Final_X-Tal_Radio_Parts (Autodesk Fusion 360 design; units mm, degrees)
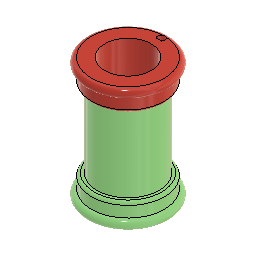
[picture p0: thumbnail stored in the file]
part number: 2026-06-11-08-03-41-367
part number: 2026-06-11-08-08-01-959
part number: 2026-06-11-08-13-43-022
part number: 2026-06-11-09-52-00-840
part number: 2026-06-11-10-06-28-813
part number: 2026-06-11-10-12-27-439
part number: 2026-06-11-10-33-16-979
part number: 2026-06-11-10-49-01-634
part number: 2026-06-11-11-00-53-288
part number: 2026-06-11-13-21-08-521
part number: 2026-06-11-14-49-13-048
sketch "Skt_SpoleForm_1C" plane through (0, 0, 0) normal (0, 0, 1) x axis (1, 0, 0)
  line L1 (0, 9) -> (0, 0)
  circle C1 centre (0, 0) radius 6
  circle C2 centre (0, 0) radius 8
  circle C3 centre (0, 0) radius 9
  circle C4 centre (0, 0) radius 5.1
  circle C5 centre (0, 7.3) radius 0.8
  circle C6 centre (0, 0) radius 6.8
  point P4 (0, 0)
  point P5 (0, 0)
  point P7 (0, 0)
  point P10 (0, 0)
  point P2 (0, 0)
  point P8 (0, 0)
  point P6 (0, 9)
  point P3 (0, 7.3)
  point P1 (0, 0)
  point P9 (0, 0)
  point P11 (0, 0)
  coincident P4 P5
  concentric C4 C6
  concentric C3 C4
  concentric C2 C6
  coincident P7 P10
  vertical L1
  concentric C1 C3
  coincident P2 P8
  coincident P6 C3
  coincident P3 L1
  coincident P1 P9
  dimension "d78" diameter C4 = 10.2
  dimension "d79" diameter C6 = 13.6
  dimension "d80" diameter C3 = 18
  dimension "d81" diameter C2 = 16
  dimension "d82" diameter C5 = 1.6
  dimension "d83" diameter C1 = 12
  dimension "d84" distance P3 P11 = 7.3
sketch "Skt_Knap_VarioCap" plane through (0, 0, 0) normal (0, 0, 1) x axis (1, 0, 0)
  line L1 (-2.6, -1.6882) -> (-2.6, 1.6882)
  circle C1 centre (0, 0) radius 10
  circle C2 centre (0, 0) radius 6
  circle C3 centre (0, 0) radius 12
  circle C4 centre (0, 0) radius 3.1
  point P2 (0, 0)
  point P3 (0, 0)
  point P7 (-2.6, 1.6882)
  point P5 (-2.6, -1.6882)
  point P4 (0, 0)
  point P1 (0, 0)
  point P6 (0, 0)
  coincident P2 P3
  coincident P7 C4
  coincident P5 C4
  vertical L1
  coincident P3 P4
  concentric C1 C4
  concentric C2 C3
  coincident P1 P6
  dimension "d85" diameter C4 = 6.2
  dimension "d86" distance P2 L1 = 2.6
  dimension "d87" diameter C2 = 12
  dimension "d88" diameter C1 = 20
  dimension "d89" diameter C3 = 24
sketch "Sketch1" plane through (0, 0, 0) normal (0, 0, 1) x axis (1, 0, 0)
  line L1 (23.2274, -19) -> (-23.2274, -19)
  line L2 (23.2274, 19) -> (-23.2274, 19)
  line L3 (30.5, 21.5) -> (-30.5, 21.5)
  line L4 (0.5, 16) -> (-23.2274, 16)
  line L5 (-30.5, 21.5) -> (30.5, -21.5)
  line L6 (-30.5, 21.5) -> (-30.5, -21.5)
  line L7 (4.5, -12) -> (4.5, 12)
  line L8 (30.5, 21.5) -> (-30.5, -21.5)
  line L9 (-30.5, -21.5) -> (30.5, -21.5)
  line L10 (0.5, -16) -> (-23.2274, -16)
  line L11 (23.2274, -16) -> (11.5, -16)
  line L12 (30.5, -21.5) -> (30.5, 21.5)
  line L13 (23.2274, 16) -> (11.5, 16)
  line L14 (7.5, -12) -> (7.5, 12)
  circle C1 centre (-26.5, -17.5) radius 3.6
  circle C2 centre (-26.5, 17.5) radius 1.6
  arc A1 centre (0.5, 12) radius 4 clockwise from (0.5, 16) to (4.5, 12)
  circle C3 centre (-26.5, -17.5) radius 1.6
  arc A2 centre (11.5, 12) radius 4 clockwise from (7.5, 12) to (11.5, 16)
  circle C4 centre (26.5, -17.5) radius 3.6
  circle C5 centre (26.5, 17.5) radius 1.6
  circle C6 centre (26.5, 17.5) radius 3.6
  circle C7 centre (26.5, -17.5) radius 1.6
  arc A3 centre (11.5, -12) radius 4 clockwise from (11.5, -16) to (7.5, -12)
  arc A4 centre (0.5, -12) radius 4 clockwise from (4.5, -12) to (0.5, -16)
  circle C8 centre (-26.5, 17.5) radius 3.6
  point P9 (0, 0)
  point P2 (0, 0)
  point P29 (-23.2274, 16)
  point P35 (23.2274, 16)
  point P28 (-23.2274, 19)
  point P27 (23.2274, 19)
  point P31 (-23.2274, -19)
  point P34 (23.2274, -19)
  point P30 (-23.2274, -16)
  point P33 (23.2274, -16)
  point P1 (0, 0)
  point P5 (-30.5, 21.5)
  point P10 (30.5, 21.5)
  point P4 (-30.5, -21.5)
  point P6 (26.5, 17.5)
  point P12 (26.5, -17.5)
  point P8 (-26.5, 17.5)
  point P7 (-26.5, -17.5)
  point P14 (26.5, 17.5)
  horizontal L9
  perpendicular L6 L9
  parallel L3 L9
  parallel L6 L12
  coincident P9 L5
  coincident P9 L8
  coincident P2 P9
  concentric C2 C8
  concentric C5 C6
  concentric C1 C3
  concentric C4 C7
  coincident P29 C8
  coincident P35 C6
  horizontal L4
  coincident P28 C8
  coincident P27 C6
  parallel L2 L3
  coincident P31 C1
  coincident P34 C4
  parallel L1 L9
  coincident P30 C1
  coincident P33 C4
  horizontal L10
  perpendicular L10 L14
  perpendicular L7 L10
  collinear L4 L13
  collinear L10 L11
  tangent A2 L14
  tangent A2 L13
  tangent A3 L14
  tangent L11 A3
  equal A2 A3
  tangent L7 A4
  tangent L10 A4
  equal A2 A4
  tangent L7 A1
  tangent L4 A1
  equal A1 A2
  coincident P1 P2
  dimension "d1" distance P5 P10 = 61
  dimension "d2" distance P4 P5 = 43
  dimension "d3" diameter C2 = 3.2
  dimension "d4" diameter C5 = 3.2
  dimension "d5" diameter C3 = 3.2
  dimension "d6" diameter C7 = 3.2
  dimension "d7" distance P6 L12 = 4
  dimension "d8" distance P12 L12 = 4 (= "d7")
  dimension "d9" distance P6 L3 = 4 (= "d7")
  dimension "d10" distance P8 L6 = 4 (= "d7")
  dimension "d11" distance P12 L9 = 4 (= "d7")
  dimension "d12" distance P7 L6 = 4 (= "d7")
  dimension "d13" distance P8 L3 = 4 (= "d7")
  dimension "d14" distance P7 L9 = 4 (= "d7")
  dimension "d15" diameter C8 = 7.2
  dimension "d16" diameter C6 = 7.2
  dimension "d17" diameter C1 = 7.2
  dimension "d18" diameter C4 = 7.2
  dimension "d19" distance L2 L4 = 3
  dimension "d20" distance P2 P14 = 17.5
  dimension "d21" distance P2 L4 = 16
  dimension "d22" distance P2 L10 = 16
  dimension "d23" distance L1 L10 = 3
  dimension "d24" distance L12 L14 = 23
  dimension "d25" distance L7 L14 = 3
  dimension "d26" radius A2 = 4
extrude "Extrude1" new body sketch "Sketch1" profile of L1 L2 L4 C1 L7 A1 L10 A2 C4 L11 C6 A3 A4 L13 L14 C8 along normal blind 1.6
extrude "Extrude2" add sketch "Sketch1" profile of C1 C2 C3 C4 C5 C6 C7 C8 along normal blind 2.4
fillet "Fillet1" radius 4
sketch "Sketch1" plane through (0, 0, 0) normal (0, 0, 1) x axis (1, 0, 0)
  line L1 (23.2274, -19) -> (-23.2274, -19)
  line L2 (23.2274, 19) -> (-23.2274, 19)
  line L3 (-30.5, 21.5) -> (-30.5, -21.5)
  line L4 (0.5, -16) -> (-23.2274, -16)
  line L5 (30.5, 21.5) -> (-30.5, 21.5)
  line L6 (30.5, -21.5) -> (30.5, 21.5)
  line L7 (-30.5, 21.5) -> (30.5, -21.5)
  line L8 (23.2274, -16) -> (11.5, -16)
  line L9 (23.2274, 16) -> (11.5, 16)
  line L10 (-30.5, -21.5) -> (30.5, -21.5)
  line L11 (30.5, 21.5) -> (-30.5, -21.5)
  line L12 (0.5, 16) -> (-23.2274, 16)
  line L13 (-26, -5) -> (-26, -13.9349)
  line L14 (-29, -4) -> (-29, -14.9096)
  line L15 (0.5, 0) -> (-25, 0)
  line L16 (26.1, 0) -> (11.5, 0)
  line L17 (7.5, 4) -> (7.5, 12)
  line L18 (7.5, -12) -> (7.5, -3)
  line L19 (4.5, 4) -> (4.5, 12)
  line L20 (4.5, -12) -> (4.5, -3)
  line L21 (27.5, -14.0417) -> (27.5, -5)
  line L22 (30.1, -4) -> (30.1, -17.5)
  line L23 (25.5, -3) -> (-24, -3)
  arc A1 centre (11.5, 12) radius 4 clockwise from (7.5, 12) to (11.5, 16)
  circle C1 centre (26.5, -17.5) radius 3.6
  arc A2 centre (0.5, -12) radius 4 clockwise from (4.5, -12) to (0.5, -16)
  circle C2 centre (26.5, 17.5) radius 3.6
  circle C3 centre (26.5, -17.5) radius 1.6
  circle C4 centre (26.5, 17.5) radius 1.6
  arc A3 centre (0.5, 12) radius 4 clockwise from (0.5, 16) to (4.5, 12)
  circle C5 centre (-26.5, 17.5) radius 3.6
  circle C6 centre (-26.5, -17.5) radius 3.6
  circle C7 centre (-26.5, -17.5) radius 1.6
  arc A4 centre (11.5, -12) radius 4 clockwise from (11.5, -16) to (7.5, -12)
  circle C8 centre (-26.5, 17.5) radius 1.6
  arc A5 centre (0.5, 4) radius 4 clockwise from (4.5, 4) to (0.5, 0)
  arc A6 centre (11.5, 4) radius 4 clockwise from (11.5, 0) to (7.5, 4)
  arc A7 centre (25.5, -5) radius 2 clockwise from (25.5, -3) to (27.5, -5)
  arc A8 centre (-25, -4) radius 4 clockwise from (-29, -4) to (-25, 0)
  arc A9 centre (-24, -5) radius 2 clockwise from (-26, -5) to (-24, -3)
  arc A10 centre (26.1, -4) radius 4 clockwise from (26.1, 0) to (30.1, -4)
  point P4 (0, 0)
  point P19 (0, 0)
  point P15 (-23.2274, 16)
  point P11 (23.2274, 16)
  point P2 (-23.2274, 19)
  point P22 (23.2274, 19)
  point P13 (-23.2274, -19)
  point P10 (23.2274, -19)
  point P12 (-23.2274, -16)
  point P14 (23.2274, -16)
  point P30 (0, 0)
  point P1 (0, 0)
  point P37 (-26, -13.9349)
  point P38 (-29, -14.9096)
  point P39 (7.5, -3)
  point P40 (4.5, -3)
  point P41 (27.5, -14.0417)
  point P42 (30.1, -17.5)
  point P9 (30.5, 21.5)
  point P21 (-30.5, 21.5)
  point P18 (-30.5, -21.5)
  point P17 (26.5, 17.5)
  point P6 (26.5, -17.5)
  point P3 (-26.5, 17.5)
  point P7 (-26.5, -17.5)
  point P31 (26.5, 17.5)
  horizontal L10
  perpendicular L3 L10
  parallel L5 L10
  parallel L3 L6
  coincident P4 L7
  coincident P4 L11
  coincident P4 P19
  concentric C5 C8
  concentric C2 C4
  concentric C6 C7
  concentric C1 C3
  coincident P15 C5
  coincident P11 C2
  horizontal L12
  coincident P2 C5
  coincident P22 C2
  parallel L2 L5
  coincident P13 C6
  coincident P10 C1
  parallel L1 L10
  coincident P12 C6
  coincident P14 C1
  horizontal L4
  perpendicular L4 L18
  perpendicular L4 L20
  collinear L9 L12
  collinear L4 L8
  tangent A1 L17
  tangent A1 L9
  tangent A4 L18
  tangent L8 A4
  equal A1 A4
  tangent A2 L20
  tangent A2 L4
  equal A1 A2
  tangent A3 L19
  tangent A3 L12
  equal A1 A3
  coincident P19 P30
  coincident P1 P30
  coincident C6 P37
  parallel L3 L13
  perpendicular L6 L16
  coincident C6 P38
  perpendicular L14 L23
  collinear L15 L16
  coincident P39 L23
  collinear L17 L18
  coincident P40 L23
  collinear L19 L20
  coincident C1 P41
  perpendicular L21 L23
  coincident C1 P42
  tangent L15 A5
  tangent L19 A5
  tangent L16 A6
  tangent L17 A6
  equal A5 A6
  tangent L21 A7
  tangent L23 A7
  tangent L15 A8
  tangent L14 A8
  tangent L23 A9
  tangent L13 A9
  tangent L22 A10
  tangent L16 A10
  dimension "d33" distance P9 P21 = 61
  dimension "d34" distance P18 P21 = 43
  dimension "d35" diameter C8 = 3.2
  dimension "d36" diameter C4 = 3.2
  dimension "d37" diameter C7 = 3.2
  dimension "d38" diameter C3 = 3.2
  dimension "d39" distance P17 L6 = 4
  dimension "d40" distance P6 L6 = 4 (= "d7")
  dimension "d41" distance P17 L5 = 4 (= "d7")
  dimension "d42" distance P3 L3 = 4 (= "d7")
  dimension "d43" distance P6 L10 = 4 (= "d7")
  dimension "d44" distance P7 L3 = 4 (= "d7")
  dimension "d45" distance P3 L5 = 4 (= "d7")
  dimension "d46" distance P7 L10 = 4 (= "d7")
  dimension "d47" diameter C5 = 7.2
  dimension "d48" diameter C2 = 7.2
  dimension "d49" diameter C6 = 7.2
  dimension "d50" diameter C1 = 7.2
  dimension "d51" distance L2 L12 = 3
  dimension "d52" distance P19 P31 = 17.5
  dimension "d53" distance P19 L12 = 16
  dimension "d54" distance P19 L4 = 16
  dimension "d55" distance L1 L4 = 3
  dimension "d56" distance L6 L17 = 23
  dimension "d57" distance L17 L19 = 3
  dimension "d58" radius A1 = 4
  dimension "d60" distance L15 L23 = 3
  dimension "d61" distance L3 L13 = 4.5
  dimension "d62" distance L13 L14 = 3
  dimension "d63" distance L6 L21 = 3
  dimension "d64" distance L6 L22 = 0.4
  dimension "d65" distance L10 L23 = 18.5
  dimension "d66" radius A5 = 4
  dimension "d67" radius A7 = 2
  dimension "d73" radius A8 = 4
  dimension "d74" radius A9 = 2
  dimension "d75" radius A10 = 4
extrude "Extrude1" new body sketch "Sketch1" profile of A1 C1 C2 L20 L2 A3 C5 C6 L18 L9 L12 L13 L23 L16 L14 L21 L22 A5 A6 A7 along normal blind 1.6
extrude "Extrude2" add sketch "Sketch1" profile of C1 C2 C3 C4 C5 C6 C7 C8 along normal blind 2.4
fillet "Fillet1" radius 4
extrude "Extrude1" new body sketch "Skt_SpoleForm_1C" profile of C2 C3 C5 along normal blind 2
extrude "Extrude2" add sketch "Skt_SpoleForm_1C" profile of C2 C5 C6 along normal blind 5
extrude "Extrude3" add sketch "Skt_SpoleForm_1C" profile of C1 C5 C6 along normal blind 22
extrude "Extrude4" add sketch "Skt_SpoleForm_1C" profile of C1 C4 along normal blind 19
fillet "Fillet1" radius 1 0.6
extrude "Extrude1" new body sketch "Skt_SpoleForm_1C" profile of C2 C3 C5 along normal blind 2
extrude "Extrude2" add sketch "Skt_SpoleForm_1C" profile of C2 C5 C6 along normal blind 5
extrude "Extrude3" add sketch "Skt_SpoleForm_1C" profile of C1 C5 C6 along normal blind 32
extrude "Extrude4" add sketch "Skt_SpoleForm_1C" profile of C1 C4 along normal blind 29
fillet "Fillet1" radius 1 0.6
extrude "Extrude1" new body sketch "Skt_SpoleForm_1C" profile of C2 C3 C5 blind -2 from offset 27
extrude "Extrude2" add sketch "Skt_SpoleForm_1C" profile of C1 C2 C5 C6 blind -5 from offset 27
extrude "Extrude3" add sketch "Skt_SpoleForm_1C" profile of C1 C4 blind -8 from offset 27
fillet "Fillet1" radius 1 0.6 0.4
sketch "Sketch1" plane through (0, 0, 0) normal (0, 0, 1) x axis (1, 0, 0)
  line L1 (33, -5) -> (33, 5)
  line L2 (32, 18) -> (28, 18)
  line L3 (35, -15) -> (35, 15)
  line L4 (27, 5) -> (27, -5)
  line L5 (17, 6) -> (17, -6)
  line L6 (13, 4) -> (-11.0133, 4)
  line L7 (25, 15) -> (25, -15)
  line L8 (32, 6) -> (28, 6)
  line L9 (17, 6) -> (-13.0201, 6)
  line L10 (13, -4) -> (13, 4)
  line L11 (17, -6) -> (-13.0201, -6)
  line L12 (-11.0133, -4) -> (13, -4)
  line L13 (28, -18) -> (32, -18)
  line L14 (28, -6) -> (32, -6)
  line L15 (-17, 0) -> (0, 0)
  circle C1 centre (30, -12) radius 1.75
  arc A1 centre (28, 15) radius 3 clockwise from (25, 15) to (28, 18)
  arc A2 centre (28, -15) radius 3 clockwise from (28, -18) to (25, -15)
  arc A3 centre (32, 15) radius 3 clockwise from (32, 18) to (35, 15)
  circle C2 centre (-17, 0) radius 7.2
  circle C3 centre (30, 12) radius 3.1
  circle C4 centre (-17, 0) radius 5.2
  circle C5 centre (30, -12) radius 3.1
  circle C6 centre (30, 12) radius 1.75
  arc A4 centre (32, -15) radius 3 clockwise from (35, -15) to (32, -18)
  arc A5 centre (32, 5) radius 1 clockwise from (32, 6) to (33, 5)
  arc A6 centre (32, -5) radius 1 clockwise from (33, -5) to (32, -6)
  arc A7 centre (28, -5) radius 1 clockwise from (28, -6) to (27, -5)
  arc A8 centre (28, 5) radius 1 clockwise from (27, 5) to (28, 6)
  point P10 (-13.0201, 6)
  point P12 (-13.0201, -6)
  point P9 (35, 18)
  point P15 (25, 18)
  point P8 (25, -18)
  point P2 (-11.0133, 4)
  point P27 (-11.0133, -4)
  point P1 (0, 0)
  point P19 (0, 0)
  point P35 (0, 0)
  point P18 (-17, 0)
  point P36 (-17, 0)
  point P11 (33, 6)
  point P16 (27, -6)
  point P13 (27, 6)
  point P3 (30, -12)
  point P4 (30, 12)
  concentric C2 C4
  coincident P10 C2
  coincident P12 C2
  horizontal L9
  horizontal L11
  vertical L5
  horizontal L2
  vertical L3
  horizontal L13
  vertical L7
  horizontal L8
  vertical L1
  horizontal L14
  vertical L4
  coincident P9 L2
  coincident P9 L3
  tangent A3 L2
  tangent A3 L3
  coincident P15 L2
  coincident P15 L7
  tangent A1 L2
  tangent A1 L7
  equal A1 A3
  coincident P8 L13
  coincident P8 L7
  tangent A2 L13
  tangent A2 L7
  equal A2 A3
  tangent L3 A4
  tangent L13 A4
  equal A3 A4
  concentric C3 C6
  concentric C1 C5
  coincident P2 C2
  horizontal L6
  perpendicular L6 L10
  coincident P27 C2
  perpendicular L10 L12
  coincident P1 P19
  coincident P1 P35
  coincident P18 P36
  horizontal L15
  coincident P11 L1
  coincident P11 L8
  coincident P16 L4
  coincident P16 L14
  coincident P13 L4
  coincident P13 L8
  tangent L1 A5
  tangent L8 A5
  tangent L1 A6
  tangent L14 A6
  equal A5 A6
  tangent L14 A7
  tangent L4 A7
  equal A5 A7
  tangent L4 A8
  tangent L8 A8
  equal A5 A8
  dimension "d129" diameter C4 = 10.4
  dimension "d130" diameter C2 = 14.4
  dimension "d131" distance P10 P12 = 12
  dimension "d132" distance P18 L11 = 6
  dimension "d133" distance P18 L5 = 34
  dimension "d134" distance P19 L5 = 17
  dimension "d135" distance P9 P15 = 10
  dimension "d136" distance P8 P15 = 36
  dimension "d137" distance P11 P13 = 6
  dimension "d138" distance P13 P16 = 12
  dimension "d139" distance L4 L7 = 2 (= "( d135 - d137 ) / 2")
  dimension "d140" distance L13 L14 = 12 (= "( d136 - d138 ) / 2")
  dimension "d141" distance P19 L2 = 18 (= "d136 / 2")
  dimension "d142" distance P19 L7 = 25
  dimension "d143" diameter C6 = 3.5
  dimension "d144" diameter C1 = 3.5
  dimension "d145" distance P3 L13 = 6 (= "d140 / 2")
  dimension "d146" distance P4 L2 = 6 (= "d140 / 2")
  dimension "d147" distance P4 L7 = 5 (= "d135 / 2")
  dimension "d148" distance P3 L7 = 5 (= "d147")
  dimension "d149" radius A3 = 3
  dimension "d150" diameter C3 = 6.2
  dimension "d151" diameter C5 = 6.2
  dimension "d152" distance L5 L10 = 4
  dimension "d153" distance L6 L9 = 2
  dimension "d154" distance L11 L12 = 2
  dimension "d255" radius A5 = 1
extrude "Extrude1" new body sketch "Sketch1" profile of C2 L5 L6 L9 L10 L11 L12 along normal blind 6
extrude "Extrude2" add sketch "Sketch1" profile of C2 C4 along normal blind 7
extrude "Extrude3" add sketch "Sketch1" profile of C4 along normal blind 1
extrude "Extrude4" add sketch "Sketch1" profile of C2 L6 L10 L12 along normal blind 2
chamfer "Chamfer1" distance 4 distance 4 Rotate Angle 45 Rotate Angle 25
fillet "Fillet1" radius 1
extrude "Extrude1" new body sketch "Sketch1" profile of A1 A2 L1 A3 L2 L3 L4 C3 C5 L7 L8 L13 A4 L14 along normal blind 5
extrude "Extrude2" add sketch "Sketch1" profile of C1 C3 C5 C6 along normal blind 2.5
extrude "Extrude3" add sketch "Sketch1" profile of L1 L4 L8 L14 along normal blind 1
chamfer "Chamfer1" distance 10 Rotate Angle 18
fillet "Fillet1" radius 1.4
sketch "Sketch1" plane through (0, 0, 0) normal (0, 0, 1) x axis (1, 0, 0)
  line L1 (-17.5, -10.9) -> (17.5, 10.9)
  line L2 (-9.5, 0) -> (-9.5, 10.9)
  line L3 (-9.5, 0) -> (-17.5, 0)
  line L4 (17.5, 14.1) -> (17.5, 10.9)
  line L5 (0, -10.9) -> (0, 0)
  line L6 (9.5, 0) -> (9.5, 10.9)
  line L7 (-9.5, 7.9) -> (-17.5, 7.9)
  line L8 (17.5, 7.9) -> (9.5, 7.9)
  line L9 (-17.5, 10.9) -> (17.5, 10.9)
  line L10 (17.5, -10.9) -> (-17.5, 10.9)
  line L11 (17.5, -10.9) -> (-17.5, -10.9)
  line L12 (-17.5, 14.1) -> (17.5, 14.1)
  line L13 (-17.5, 10.9) -> (-17.5, 14.1)
  line L14 (17.5, 10.9) -> (17.5, -10.9)
  line L15 (-17.5, -10.9) -> (-17.5, 10.9)
  line L16 (9.5, 0.9) -> (-9.5, 0.9)
  line L17 (17.5, 0) -> (9.5, 0)
  circle C1 centre (-14, -6.4) radius 1.5
  circle C2 centre (14, -6.4) radius 1.5
  circle C3 centre (0, -6.4) radius 10
  point P7 (0, 0)
  point P2 (0, 0)
  point P13 (9.5, 10.9)
  point P14 (-9.5, 10.9)
  point P16 (17.5, 0)
  point P17 (-17.5, 0)
  point P11 (-9.5, 0.9)
  point P19 (9.5, 0.9)
  point P20 (9.5, 7.9)
  point P22 (17.5, 7.9)
  point P18 (-17.5, 7.9)
  point P21 (-9.5, 7.9)
  point P23 (0, 0)
  point P26 (0, -10.9)
  point P25 (0, -6.4)
  point P1 (0, 0)
  point P4 (17.5, -10.9)
  point P6 (-17.5, -10.9)
  point P5 (-17.5, 10.9)
  point P3 (17.5, 10.9)
  point P9 (-17.5, 14.1)
  point P10 (14, -6.4)
  point P24 (-14, -6.4)
  horizontal L9
  perpendicular L9 L15
  parallel L9 L11
  parallel L14 L15
  coincident P7 L1
  coincident P7 L10
  coincident P2 P7
  vertical L4
  horizontal L12
  vertical L13
  coincident P13 L9
  perpendicular L6 L11
  coincident P14 L9
  perpendicular L2 L11
  perpendicular L14 L17
  midpoint P16 L14
  midpoint P17 L15
  horizontal L3
  coincident P11 L2
  coincident P19 L6
  perpendicular L6 L16
  coincident P20 L6
  coincident P22 L14
  perpendicular L8 L14
  coincident P18 L15
  coincident P21 L2
  perpendicular L2 L7
  coincident P7 P23
  midpoint P26 L11
  coincident P25 L5
  coincident P1 P7
  dimension "d192" distance P4 P6 = 35
  dimension "d193" distance P5 P6 = 21.8 (= "25 mm - d195")
  dimension "d194" distance P3 P5 = 35
  dimension "d195" distance P5 P9 = 3.2
  dimension "d196" diameter C2 = 3
  dimension "d197" diameter C1 = 3 (= "d196")
  dimension "d198" distance P10 L14 = 3.5
  dimension "d199" distance P24 L15 = 3.5 (= "d198")
  dimension "d200" distance P10 L11 = 4.5
  dimension "d201" distance P24 L11 = 4.5 (= "d200")
  dimension "d202" distance L6 L14 = 8
  dimension "d203" distance L2 L15 = 8 (= "d202")
  dimension "d204" distance L9 L16 = 10
  dimension "d205" distance L7 L9 = 3 (= "d206")
  dimension "d206" distance L8 L9 = 3
  dimension "d207" diameter C3 = 20
  dimension "d208" distance P25 L11 = 4.5 (= "d200")
extrude "Extrude1" new body sketch "Sketch1" profile of L2 L3 C1 C2 L6 C3 L11 L14 L15 L16 L17 along normal blind 3.2
extrude "Extrude2" add sketch "Sketch1" profile of L2 L3 L6 L7 L8 L9 L14 L15 L17 along normal blind 6.2
extrude "Extrude3" add sketch "Sketch1" profile of L2 L6 C3 L9 L16 along normal blind 10.2
extrude "Extrude4" add sketch "Sketch1" profile of L4 L9 L12 L13 along normal blind 21
sketch "Sketch2" plane through (0, 10.9, 0) normal (0, -1, 0) x axis (1, 0, 0)
  line L1 (17.5, 6.2) -> (9.5, 6.2)
  line L2 (17.5, 21) -> (17.5, 6.2)
  line L3 (-17.5, 21) -> (17.5, 21)
  line L4 (-17.5, 6.2) -> (-17.5, 21)
  line L5 (-9.5, 6.2) -> (-17.5, 6.2)
  line L6 (-9.5, 10.2) -> (-9.5, 6.2)
  line L7 (9.5, 10.2) -> (-9.5, 10.2)
  line L8 (9.5, 6.2) -> (9.5, 10.2)
  line L9 (-9.5, 10.2) -> (-9.5, 6.2)
  line L10 (9.5, 6.2) -> (9.5, 10.2)
  line L11 (9.5, 10.2) -> (-9.5, 10.2)
  line L12 (17.5, 6.2) -> (9.5, 6.2)
  line L13 (-17.5, 21) -> (17.5, 21)
  line L14 (-17.5, 6.2) -> (-17.5, 21)
  line L15 (-9.5, 6.2) -> (-17.5, 6.2)
  line L16 (17.5, 21) -> (17.5, 6.2)
  line L17 (-10, 0) -> (10, 0)
  circle C1 centre (-14, 11) radius 1.6
  circle C2 centre (14, 11) radius 1.6
  point P14 (14, 11)
  point P13 (-14, 11)
  point P20 (0, 0)
  dimension "d217" diameter C1 = 3.2
  dimension "d218" diameter C2 = 3.2
  dimension "d219" distance P14 L13 = 10
  dimension "d220" distance P13 L13 = 10 (= "d219")
  dimension "d221" distance P13 P20 = 14
  dimension "d222" distance P14 P20 = 14
  dimension "d223" distance L13 L17 = 21
extrude "Extrude5" cut sketch "Sketch2" profile of C1 C2 no distance stored
chamfer "Chamfer1" distance 7
fillet "Fillet1" radius 9
fillet "Fillet2" radius 2
chamfer "Chamfer2" distance 10.5 distance 2.5
fillet "Fillet3" radius 1
extrude "Extrude6" cut sketch "Sketch1" profile of C3 L16 blind 3 from offset 3.2
fillet "Fillet4" radius 2
extrude "Extrude1" new body sketch "Skt_Knap_VarioCap" profile of C1 C3 along normal blind 10
extrude "Extrude2" add sketch "Skt_Knap_VarioCap" profile of C1 C2 along normal blind 5
extrude "Extrude3" add sketch "Skt_Knap_VarioCap" profile of C2 C4 along normal blind 12
extrude "Extrude4" add sketch "Skt_Knap_VarioCap" profile of L1 C4 along normal blind 11
extrude "Extrude5" add sketch "Skt_Knap_VarioCap" profile of L1 C4 along normal blind 5
fillet "Fillet1" radius 1
fillet "Fillet2" radius 0.4
fillet "Fillet3" radius 1
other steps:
create_component "CreateComponent1"
create_component "CreateComponent2"
create_component "CreateComponent3"
create_component "CreateComponent4"
create_component "CreateComponent5"
create_component "CreateComponent6"
create_component "CreateComponent1"
create_component "CreateComponent2"
create_component "CreateComponent7"
create_component "CreateComponent8"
